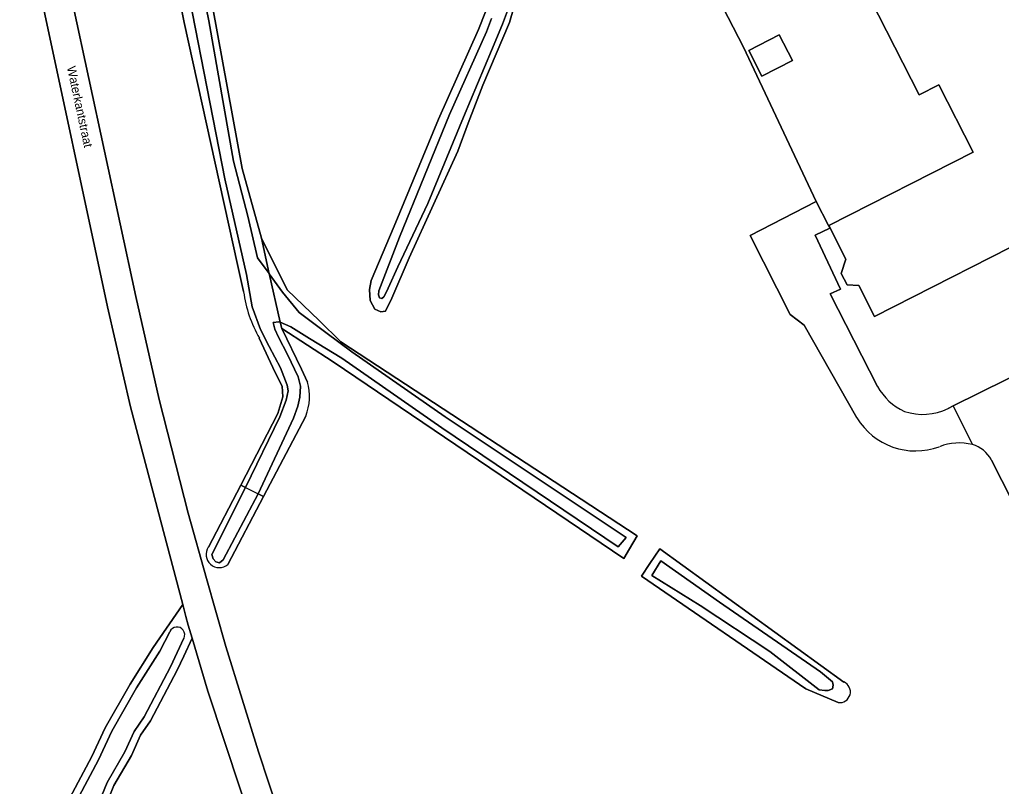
# Model space of a CAD drawing. Extents: x 158132 to 159664, y 385256 to 387218.
# Drawn here: x 158730.1 to 158842, y 386267.5 to 386355 of the extents above; entities that cross this region are included whole.
import ezdxf

# ---------------------------------------------------------------- set-up
doc = ezdxf.new("R2010")
doc.units = 0
for name, color, linetype in [('IMGEO_Erf', 7, 'Continuous'), ('IMGEO_Gemengd_bos', 7, 'Continuous'), ('IMGEO_Oever', 7, 'Continuous'), ('IMGEO_Openbare_ruimte_label', 7, 'Continuous'), ('IMGEO_Pand', 7, 'Continuous'), ('IMGEO_Rijbaan_lokaal_gesloten', 7, 'Continuous'), ('IMGEO_Stuw', 7, 'Continuous'), ('IMGEO_Waterloop', 7, 'Continuous')]:
    doc.layers.add(name, color=color, linetype=linetype)

msp = doc.modelspace()

# ---------------------------------------------------------------- linework, layer by layer
at = {"layer": 'IMGEO_Erf'}
for points in [[(158847.47, 386331.21), (158827.59, 386321.1), (158825.78, 386324.64), (158824.45, 386324.71), (158823.78, 386326.03), (158824.31, 386327.66), (158822.36, 386331.49), (158838.82, 386339.86), (158834.91, 386347.54), (158832.68, 386346.41), (158826.18, 386359.19), (158831.64, 386361.96), (158831.38, 386362.48), (158832.15, 386363.66), (158833.46, 386364.27), (158834.5, 386364.17), (158834.78, 386363.61), (158838.56, 386365.53), (158838.65, 386365.34), (158840.59, 386361.52), (158847.51, 386347.83)], [(158807.4, 386362.02), (158812.65, 386351.84), (158820.91, 386334.22), (158822.33, 386331.48), (158822.48, 386331.19), (158820.8, 386330.39), (158823.69, 386324.25), (158822.51, 386323.69), (158827.93, 386313.14)], [(158835.97, 386310.61), (158836.56, 386310.91), (158848.8, 386316.98), (158849.85, 386317.5), (158850.54, 386317.85), (158851.32, 386316.42), (158858.61, 386320.03), (158859.72, 386322.15), (158861.09, 386324.79), (158861.16, 386324.95), (158861.22, 386325.11), (158861.27, 386325.28), (158861.3, 386325.45), (158861.32, 386325.62), (158861.32, 386325.79), (158861.31, 386325.97), (158861.28, 386326.14), (158861.24, 386326.3), (158860.71, 386327.59), (158861.38, 386328.03)]]:
    msp.add_lwpolyline(points, dxfattribs=at)
msp.add_lwpolyline([(158814.74, 386348.53), (158813.24, 386351.47), (158816.72, 386353.24), (158818.21, 386350.3)], close=True, dxfattribs=at)
for centre, radius, start, end in [((158833.58, 386316.16), 6.41, 208.1389, 246.3094), ((158833.1, 386316.54), 6.59, 251.4809, 295.8313)]:
    msp.add_arc(centre, radius, start, end, dxfattribs=at)
at = {"layer": 'IMGEO_Gemengd_bos'}
for points in [[(158755.63, 386323.95), (158754.93, 386327.04), (158748.86, 386354.64), (158743.31, 386382.56), (158739.24, 386402.17), (158735.92, 386419.01), (158735.24, 386422.5), (158734.72, 386424.99), (158734.55, 386427.23), (158734.67, 386429.11), (158735.15, 386431.32), (158736.09, 386433.56), (158738.64, 386438.6), (158746.9, 386455.19)], [(158739.51, 386424.44), (158744.28, 386399.14), (158755.47, 386338)], [(158825.57, 386309.56), (158819.55, 386320.12), (158817.96, 386321.33), (158813.41, 386330.36), (158820.91, 386334.22), (158812.65, 386351.84), (158807.4, 386362.02), (158804.59, 386367.48), (158810.99, 386370.77), (158805.6, 386381.25), (158821.82, 386389.61)], [(158734.4, 386364.89), (158743.33, 386323.41), (158746.02, 386311.65), (158749.3, 386298.68), (158751.42, 386291.23), (158753.61, 386283.48), (158757.33, 386271.45), (158764.42, 386250), (158774.64, 386219.06)], [(158730.77, 386256.7), (158738.34, 386270.94), (158739.86, 386274.2), (158742.7, 386279.18), (158745.33, 386283.37), (158748.7, 386288.27), (158742.74, 386310.8), (158740.13, 386322.23), (158732.17, 386359.37)], [(158786.45, 386356.36), (158785.97, 386354.65), (158782.9, 386347.5), (158781.24, 386343.16), (158780.07, 386339.98), (158774.51, 386327.8), (158772.53, 386323.22), (158771.8, 386321.74), (158771.3, 386321.66), (158770.6, 386321.95), (158770.06, 386322.94), (158770, 386324.21), (158770.2, 386325.22), (158772.81, 386331.43), (158777.87, 386343.64), (158782.41, 386353.87), (158783.93, 386357.73)], [(158755.47, 386338), (158757.66, 386330.04), (158760.61, 386324.15), (158764.27, 386320.67), (158766.74, 386318.22), (158800.53, 386296.11), (158799.65, 386294.62), (158799, 386293.52), (158765.85, 386315.95), (158759.98, 386319.75), (158762.25, 386315.12), (158762.93, 386313.64)], [(158751.62, 386294.81), (158755.31, 386301.89), (158759.55, 386310.04), (158760.12, 386311.96), (158760.02, 386313.17), (158759.23, 386314.72), (158757.43, 386318.65)], [(158762.73, 386309.75), (158757.91, 386300.57), (158753.84, 386292.83)], [(158855.71, 386275.53), (158850.93, 386273.25), (158849.14, 386277.02), (158853.88, 386279.22), (158840.91, 386304.74)], [(158823.43, 386277.08), (158819.76, 386278.65), (158800.99, 386291.51), (158801.96, 386292.95), (158803.09, 386294.63), (158824.07, 386279.42)], [(158760.94, 386250), (158751.56, 386278.38), (158749.77, 386284.41), (158748.81, 386282.37), (158748.06, 386280.76), (158745.01, 386275), (158743.88, 386273.35), (158742.84, 386271.05), (158740.85, 386267.6), (158740.24, 386266.08)]]:
    msp.add_lwpolyline(points, dxfattribs=at)
for centre, radius, start, end in [((158770.02, 386325.89), 14.52, 187.7089, 209.9317), ((158756.71, 386312.01), 6.44, 339.4508, 14.6258), ((158832.26, 386313.6), 7.82, 211.1443, 290.2723), ((158837.23, 386300.47), 6.22, 75.9296, 111.2949), ((158837.79, 386303.13), 3.51, 27.4626, 74.4113), ((158752.86, 386293.97), 1.5, 146.1552, 310.4752), ((158823.61, 386278.29), 1.22, 261.507, 67.9497)]:
    msp.add_arc(centre, radius, start, end, dxfattribs=at)
at = {"layer": 'IMGEO_Oever'}
for points in [[(158746.9, 386455.19), (158738.64, 386438.6), (158736.09, 386433.56), (158735.15, 386431.32), (158734.67, 386429.11), (158734.55, 386427.23), (158734.72, 386424.99), (158735.24, 386422.5), (158735.92, 386419.01), (158739.24, 386402.17), (158743.31, 386382.56), (158748.86, 386354.64), (158754.93, 386327.04), (158755.63, 386323.95)], [(158749.3, 386453.83), (158741.69, 386438.9), (158739.08, 386433.62), (158738.24, 386431.21), (158737.93, 386429.5), (158737.75, 386427.7), (158738.25, 386424.73), (158740.93, 386411.36), (158742.95, 386400.97), (158745.84, 386384.66), (158748.64, 386369.72), (158751.69, 386354.85), (158754.48, 386338.82), (158756.11, 386332.57), (158757.24, 386327.82), (158758.56, 386326.01), (158758.57, 386325.99)], [(158758.57, 386325.99), (158757.66, 386330.04), (158755.47, 386338), (158744.28, 386399.14), (158739.51, 386424.44)], [(158757.43, 386318.65), (158759.23, 386314.72), (158760.02, 386313.17), (158760.12, 386311.96), (158759.55, 386310.04), (158755.31, 386301.89), (158755.86, 386301.61), (158759.76, 386309.67), (158760.48, 386311.56), (158760.7, 386312.64), (158760.61, 386313.27), (158759.84, 386315.24), (158758.56, 386317.68), (158757.58, 386319.65), (158756.63, 386322.21), (158755.98, 386325.92), (158753.51, 386336.81), (158747.76, 386366.21)], [(158783.93, 386357.73), (158782.41, 386353.87), (158777.87, 386343.64), (158772.81, 386331.43), (158770.2, 386325.22), (158770, 386324.21), (158770.06, 386322.94), (158770.6, 386321.95), (158771.3, 386321.66), (158771.8, 386321.74), (158772.53, 386323.22), (158774.51, 386327.8), (158780.07, 386339.98), (158781.24, 386343.16), (158782.9, 386347.5), (158785.97, 386354.65), (158786.45, 386356.36)], [(158785.85, 386356.27), (158785.17, 386354.46), (158783.9, 386351.44), (158780.71, 386343.87), (158776.63, 386333.99), (158773.23, 386326.78), (158772.12, 386324.35), (158771.84, 386323.77), (158771.62, 386323.34), (158771.41, 386323.15), (158771.15, 386323.25), (158771.02, 386323.58), (158771.04, 386324.06), (158773.43, 386330.15), (158779.11, 386344.16), (158783.34, 386353.57), (158783.9, 386355.1)], [(158759.98, 386319.75), (158759.82, 386320.45), (158759.81, 386320.45), (158759.65, 386320.52), (158759.01, 386320.42), (158759.18, 386319.68), (158759.62, 386318.76), (158760.63, 386316.77), (158761.85, 386314.25), (158762.11, 386313.17), (158762.04, 386311.91), (158761.81, 386310.87), (158761.32, 386309.5), (158757.3, 386300.88), (158757.91, 386300.57), (158762.73, 386309.75)], [(158762.93, 386313.64), (158762.25, 386315.12), (158759.98, 386319.75)], [(158757.91, 386300.57), (158757.3, 386300.88), (158753.32, 386293.34), (158752.89, 386293.01), (158752.47, 386293.11), (158752.17, 386293.48), (158752.03, 386293.96), (158755.86, 386301.61), (158755.31, 386301.89), (158751.62, 386294.81)], [(158753.84, 386292.83), (158757.91, 386300.57)], [(158803.09, 386294.63), (158801.96, 386292.95), (158800.99, 386291.51), (158819.76, 386278.65), (158823.43, 386277.08)], [(158824.07, 386279.42), (158803.09, 386294.63)], [(158740.24, 386266.08), (158740.85, 386267.6), (158742.84, 386271.05), (158743.88, 386273.35), (158745.01, 386275), (158748.06, 386280.76), (158748.81, 386282.37), (158749.77, 386284.41), (158749.33, 386285.89), (158749.06, 386286.9), (158748.7, 386288.27), (158745.33, 386283.37), (158742.7, 386279.18), (158739.86, 386274.2), (158738.34, 386270.94), (158730.77, 386256.7)], [(158730.1, 386252.86), (158731.54, 386256.33), (158739.1, 386270.56), (158740.62, 386273.81), (158743.43, 386278.75), (158746.07, 386282.95), (158747.22, 386285.16)], [(158748.84, 386284.43), (158747.3, 386281.14), (158744.29, 386275.44), (158743.14, 386273.77), (158742.08, 386271.44), (158740.08, 386267.97), (158739.47, 386266.46), (158737.86, 386263.79), (158733.56, 386255.44)]]:
    msp.add_lwpolyline(points, dxfattribs=at)
for points in [[(158757.66, 386330.04), (158758.57, 386325.99), (158760.09, 386323.89), (158761.96, 386321.58), (158765.03, 386319.3), (158767.97, 386317.08), (158778.63, 386309.67), (158799.25, 386295.89), (158798.36, 386294.83), (158778.23, 386308.43), (158766.84, 386316.37), (158763.16, 386318.61), (158761.02, 386319.93), (158759.82, 386320.45), (158759.98, 386319.75), (158765.85, 386315.95), (158799, 386293.52), (158799.65, 386294.62), (158800.53, 386296.11), (158766.74, 386318.22), (158764.27, 386320.67), (158760.61, 386324.15)], [(158809.92, 386288.52), (158821.41, 386280.57), (158822.78, 386279.44), (158822.85, 386279.06), (158822.8, 386278.65), (158822.28, 386278.47), (158821.9, 386278.46), (158821.28, 386278.52), (158815.66, 386282.9), (158807.68, 386288.16), (158802.19, 386291.57), (158803.2, 386293.25)]]:
    msp.add_lwpolyline(points, close=True, dxfattribs=at)
for centre, radius, start, end in [((158770.02, 386325.89), 14.52, 187.7089, 209.9317), ((158756.71, 386312.01), 6.44, 339.4508, 14.6258), ((158752.86, 386293.97), 1.5, 146.1552, 310.4752), ((158748.04, 386284.81), 0.887, 335.1598, 156.5939), ((158823.61, 386278.29), 1.22, 261.507, 67.9497)]:
    msp.add_arc(centre, radius, start, end, dxfattribs=at)
at = {"layer": 'IMGEO_Pand'}
msp.add_lwpolyline([(158847.51, 386347.83), (158840.59, 386361.52), (158838.65, 386365.34), (158838.56, 386365.53), (158834.78, 386363.61), (158834.5, 386364.17), (158833.46, 386364.27), (158832.15, 386363.66), (158831.38, 386362.48), (158831.64, 386361.96), (158826.18, 386359.19), (158832.68, 386346.41), (158834.91, 386347.54), (158838.82, 386339.86), (158822.36, 386331.49), (158824.31, 386327.66), (158823.78, 386326.03), (158824.45, 386324.71), (158825.78, 386324.64), (158827.59, 386321.1), (158847.47, 386331.21)], dxfattribs=at)
msp.add_lwpolyline([(158814.74, 386348.53), (158818.21, 386350.3), (158816.72, 386353.24), (158813.24, 386351.47)], close=True, dxfattribs=at)
at = {"layer": 'IMGEO_Rijbaan_lokaal_gesloten'}
for points in [[(158764.42, 386250), (158757.33, 386271.45), (158753.61, 386283.48), (158751.42, 386291.23), (158749.3, 386298.68), (158746.02, 386311.65), (158743.33, 386323.41), (158734.4, 386364.89)], [(158732.17, 386359.37), (158740.13, 386322.23), (158742.74, 386310.8), (158748.7, 386288.27), (158749.06, 386286.9), (158749.33, 386285.89), (158749.77, 386284.41), (158751.56, 386278.38), (158760.94, 386250), (158771.5, 386218.02), (158774.64, 386219.06), (158764.42, 386250)], [(158820.91, 386334.22), (158813.41, 386330.36), (158817.96, 386321.33), (158819.55, 386320.12), (158825.57, 386309.56)], [(158827.93, 386313.14), (158822.51, 386323.69), (158823.69, 386324.25), (158820.8, 386330.39), (158822.48, 386331.19), (158822.33, 386331.48), (158820.91, 386334.22)], [(158867.89, 386328.69), (158861.38, 386328.03), (158860.71, 386327.59), (158861.24, 386326.3), (158861.28, 386326.14), (158861.31, 386325.97), (158861.32, 386325.79), (158861.32, 386325.62), (158861.3, 386325.45), (158861.27, 386325.28), (158861.22, 386325.11), (158861.16, 386324.95), (158861.09, 386324.79), (158859.72, 386322.15), (158858.61, 386320.03), (158851.32, 386316.42), (158850.54, 386317.85), (158849.85, 386317.5), (158848.8, 386316.98), (158836.56, 386310.91), (158838.74, 386306.51)], [(158838.74, 386306.51), (158836.56, 386310.91), (158835.97, 386310.61)], [(158840.91, 386304.74), (158853.88, 386279.22), (158855.22, 386276.57)]]:
    msp.add_lwpolyline(points, dxfattribs=at)
for centre, radius, start, end in [((158833.58, 386316.16), 6.41, 208.1389, 246.3094), ((158833.1, 386316.54), 6.59, 251.4809, 295.8313), ((158832.26, 386313.6), 7.82, 211.1443, 290.2723), ((158837.23, 386300.47), 6.22, 75.9296, 111.2949), ((158837.79, 386303.13), 3.51, 27.4626, 74.4113)]:
    msp.add_arc(centre, radius, start, end, dxfattribs=at)
at = {"layer": 'IMGEO_Stuw'}
msp.add_lwpolyline([(158755.31, 386301.89), (158757.91, 386300.57)], dxfattribs=at)
at = {"layer": 'IMGEO_Waterloop'}
for points in [[(158747.76, 386366.21), (158753.51, 386336.81), (158755.98, 386325.92), (158756.63, 386322.21), (158757.58, 386319.65), (158758.56, 386317.68), (158759.84, 386315.24), (158760.61, 386313.27), (158760.7, 386312.64), (158760.48, 386311.56), (158759.76, 386309.67), (158755.86, 386301.61), (158752.03, 386293.96), (158752.17, 386293.48), (158752.47, 386293.11), (158752.89, 386293.01), (158753.32, 386293.34), (158757.3, 386300.88), (158761.32, 386309.5), (158761.81, 386310.87), (158762.04, 386311.91), (158762.11, 386313.17), (158761.85, 386314.25), (158760.63, 386316.77), (158759.62, 386318.76), (158759.18, 386319.68), (158759.01, 386320.42), (158759.65, 386320.52), (158759.81, 386320.45), (158758.56, 386326.01), (158757.24, 386327.82), (158756.11, 386332.57), (158754.48, 386338.82), (158751.69, 386354.85), (158748.64, 386369.72)], [(158783.9, 386355.1), (158783.34, 386353.57), (158779.11, 386344.16), (158773.43, 386330.15), (158771.04, 386324.06), (158771.02, 386323.58), (158771.15, 386323.25), (158771.41, 386323.15), (158771.62, 386323.34), (158771.84, 386323.77), (158772.12, 386324.35), (158773.23, 386326.78), (158776.63, 386333.99), (158780.71, 386343.87), (158783.9, 386351.44), (158785.17, 386354.46), (158785.85, 386356.27)], [(158747.22, 386285.16), (158746.07, 386282.95), (158743.43, 386278.75), (158740.62, 386273.81), (158739.1, 386270.56), (158731.54, 386256.33), (158730.1, 386252.86)], [(158733.56, 386255.44), (158737.86, 386263.79), (158739.47, 386266.46), (158740.08, 386267.97), (158742.08, 386271.44), (158743.14, 386273.77), (158744.29, 386275.44), (158747.3, 386281.14), (158748.84, 386284.43)]]:
    msp.add_lwpolyline(points, dxfattribs=at)
for points in [[(158778.63, 386309.67), (158767.97, 386317.08), (158765.03, 386319.3), (158761.96, 386321.58), (158760.09, 386323.89), (158758.57, 386325.99), (158758.56, 386326.01), (158759.81, 386320.45), (158759.82, 386320.45), (158761.02, 386319.93), (158763.16, 386318.61), (158766.84, 386316.37), (158778.23, 386308.43), (158798.36, 386294.83), (158799.25, 386295.89)], [(158809.92, 386288.52), (158803.2, 386293.25), (158802.19, 386291.57), (158807.68, 386288.16), (158815.66, 386282.9), (158821.28, 386278.52), (158821.9, 386278.46), (158822.28, 386278.47), (158822.8, 386278.65), (158822.85, 386279.06), (158822.78, 386279.44), (158821.41, 386280.57)]]:
    msp.add_lwpolyline(points, close=True, dxfattribs=at)
msp.add_arc((158748.04, 386284.81), 0.887, 335.1598, 156.5939, dxfattribs=at)

# ---------------------------------------------------------------- texts
at = {"layer": 'IMGEO_Openbare_ruimte_label'}
msp.add_text('Waterkantstraat', height=1, rotation=282.1308, dxfattribs=at).set_placement((158735.48, 386349.55))

doc.saveas('drawing.dxf')
